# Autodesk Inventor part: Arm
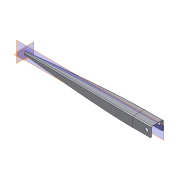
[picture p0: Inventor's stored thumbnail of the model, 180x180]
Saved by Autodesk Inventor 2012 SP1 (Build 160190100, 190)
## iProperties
Created: 2006-03
Part Number: Arm
Document SubType Name: Modeling
Material: Stainless Steel, 440C
Mass: 106.48 g
Surface Area: 286.369 cm^2
Volume: 13.7394 cm^3
Density: 7.75 g/cm^3
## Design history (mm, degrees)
sketch "Sketch1"
  geometry: L1 (-13.5, 11)-(13.5, 11); L2 (13.5, 11)-(13.5, -11); L3 (13.5, -11)-(-13.5, -11); L4 (-13.5, -11)-(-13.5, 11); L5 (-13.5, 11)-(13.5, -11); 2 further points
  constraints: 10 end point, 2 parallel, 1 coincident, 1 horizontal, 1 midpoint, 1 perpendicular
  dimensions: "d0" = 27 distance of L1.start L1.end; "d1" = 22 distance of L3.end L1.start
extrude "Extrusion1" new body sketch "Sketch1" distance "d2" = 40; taper "d3" = 0 deg
workplane "Work Plane1"
sketch "Sketch2"
  geometry: L1 (-2.5, 2.5)-(2.5, 2.5); L2 (2.5, 2.5)-(2.5, -2.5); L3 (2.5, -2.5)-(-2.5, -2.5); L4 (-2.5, -2.5)-(-2.5, 2.5); L5 (-2.5, 2.5)-(2.5, -2.5); 2 further points
  constraints: 10 end point, 2 parallel, 2 perpendicular, 1 coincident, 1 horizontal, 1 midpoint
  dimensions: "d5" = 5 distance of L1.start L1.end
loft "Loft1" sketch "Sketch2" dims "d6" = 10, "d7" = 90 deg, "d8" = 10, "d9" = 90 deg
  node "Edges1"
shell "Shell1" dims "d10" = 1
sketch "Sketch3"
  geometry: L1 (-52, 0)-(4, 0) reference; L2 (-40, 10)-(-40, -11) reference; C1 r 4 at (-30, 0); 1 further point
  constraints: 1 centre point, 1 point on line
  dimensions: "d11" = 10 distance from line of C1.centre L2; "d16" = 8 diameter of C1
extrude "Extrusion2" cut sketch "Sketch3" stored distance "d12" = 40; taper "d13" = 0 deg
fillet "Fillet1" dims "d14" = 2
fillet "Fillet2" dims "d15" = 2
workplane "Work Plane2"
workplane "Work Plane3"
body "Solid1"
